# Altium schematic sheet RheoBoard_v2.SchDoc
size A0; SheetNumber: 1; SheetTotal: 3
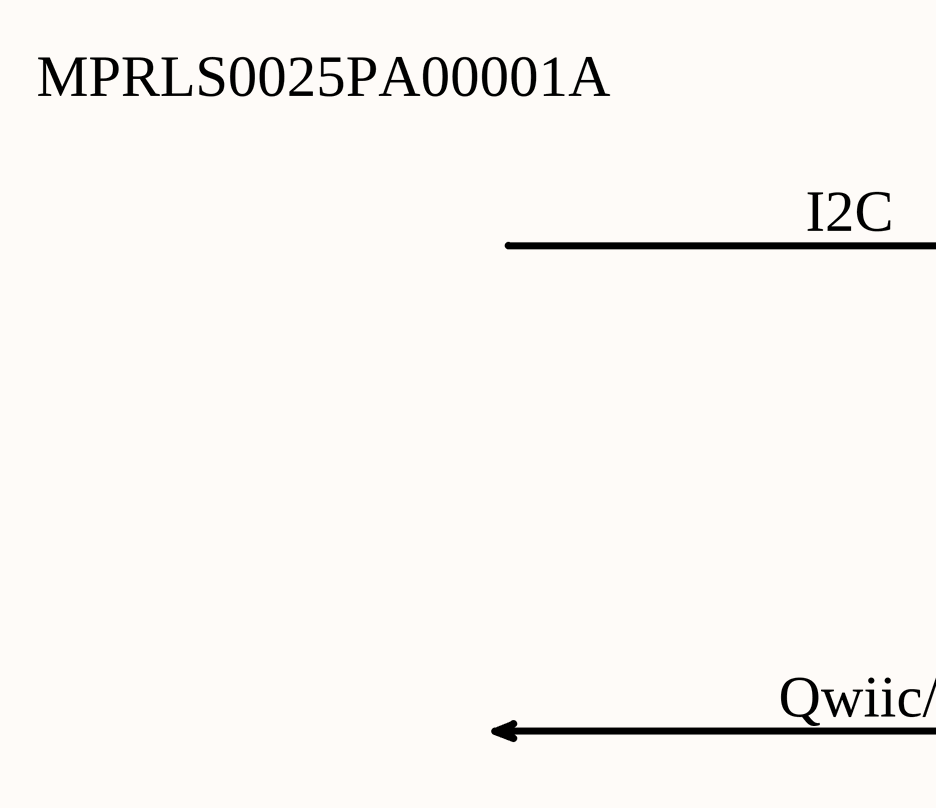
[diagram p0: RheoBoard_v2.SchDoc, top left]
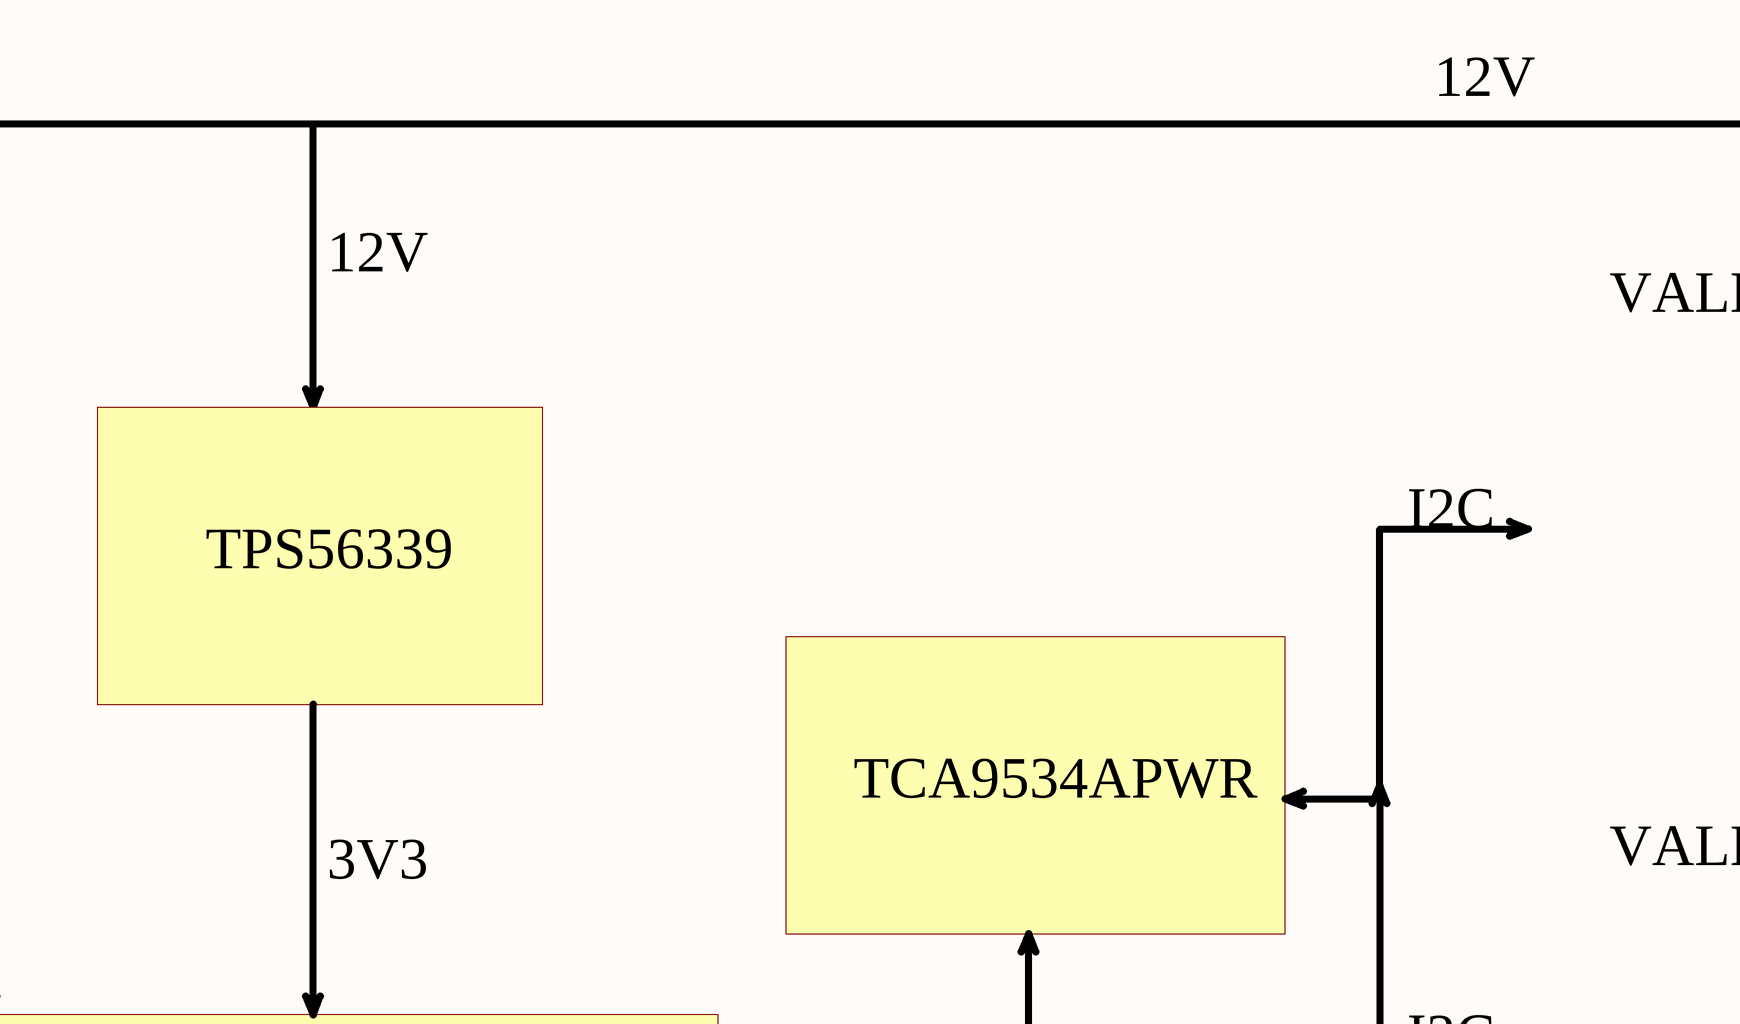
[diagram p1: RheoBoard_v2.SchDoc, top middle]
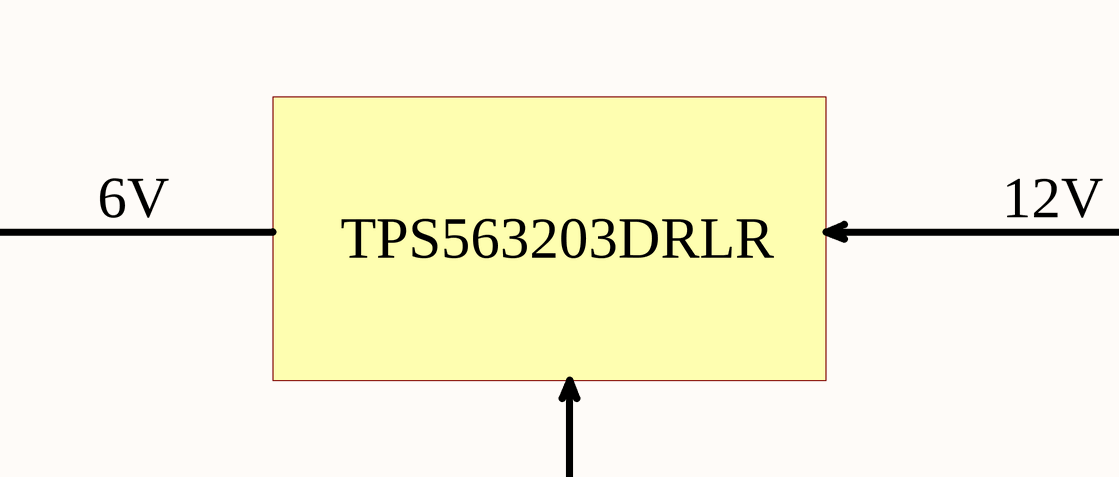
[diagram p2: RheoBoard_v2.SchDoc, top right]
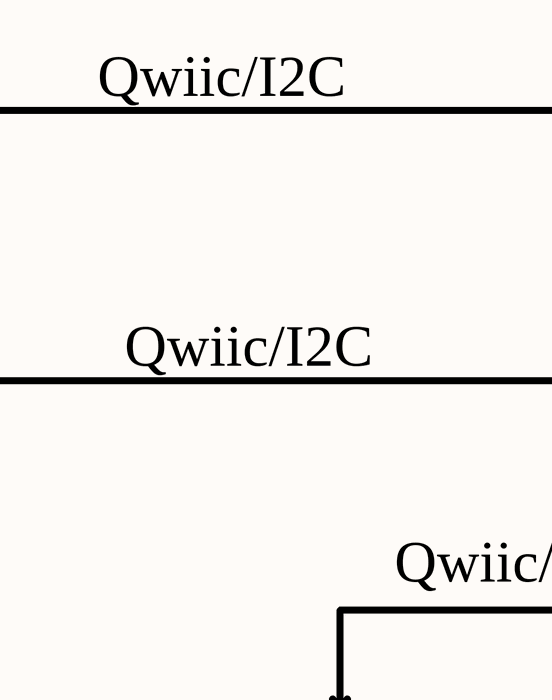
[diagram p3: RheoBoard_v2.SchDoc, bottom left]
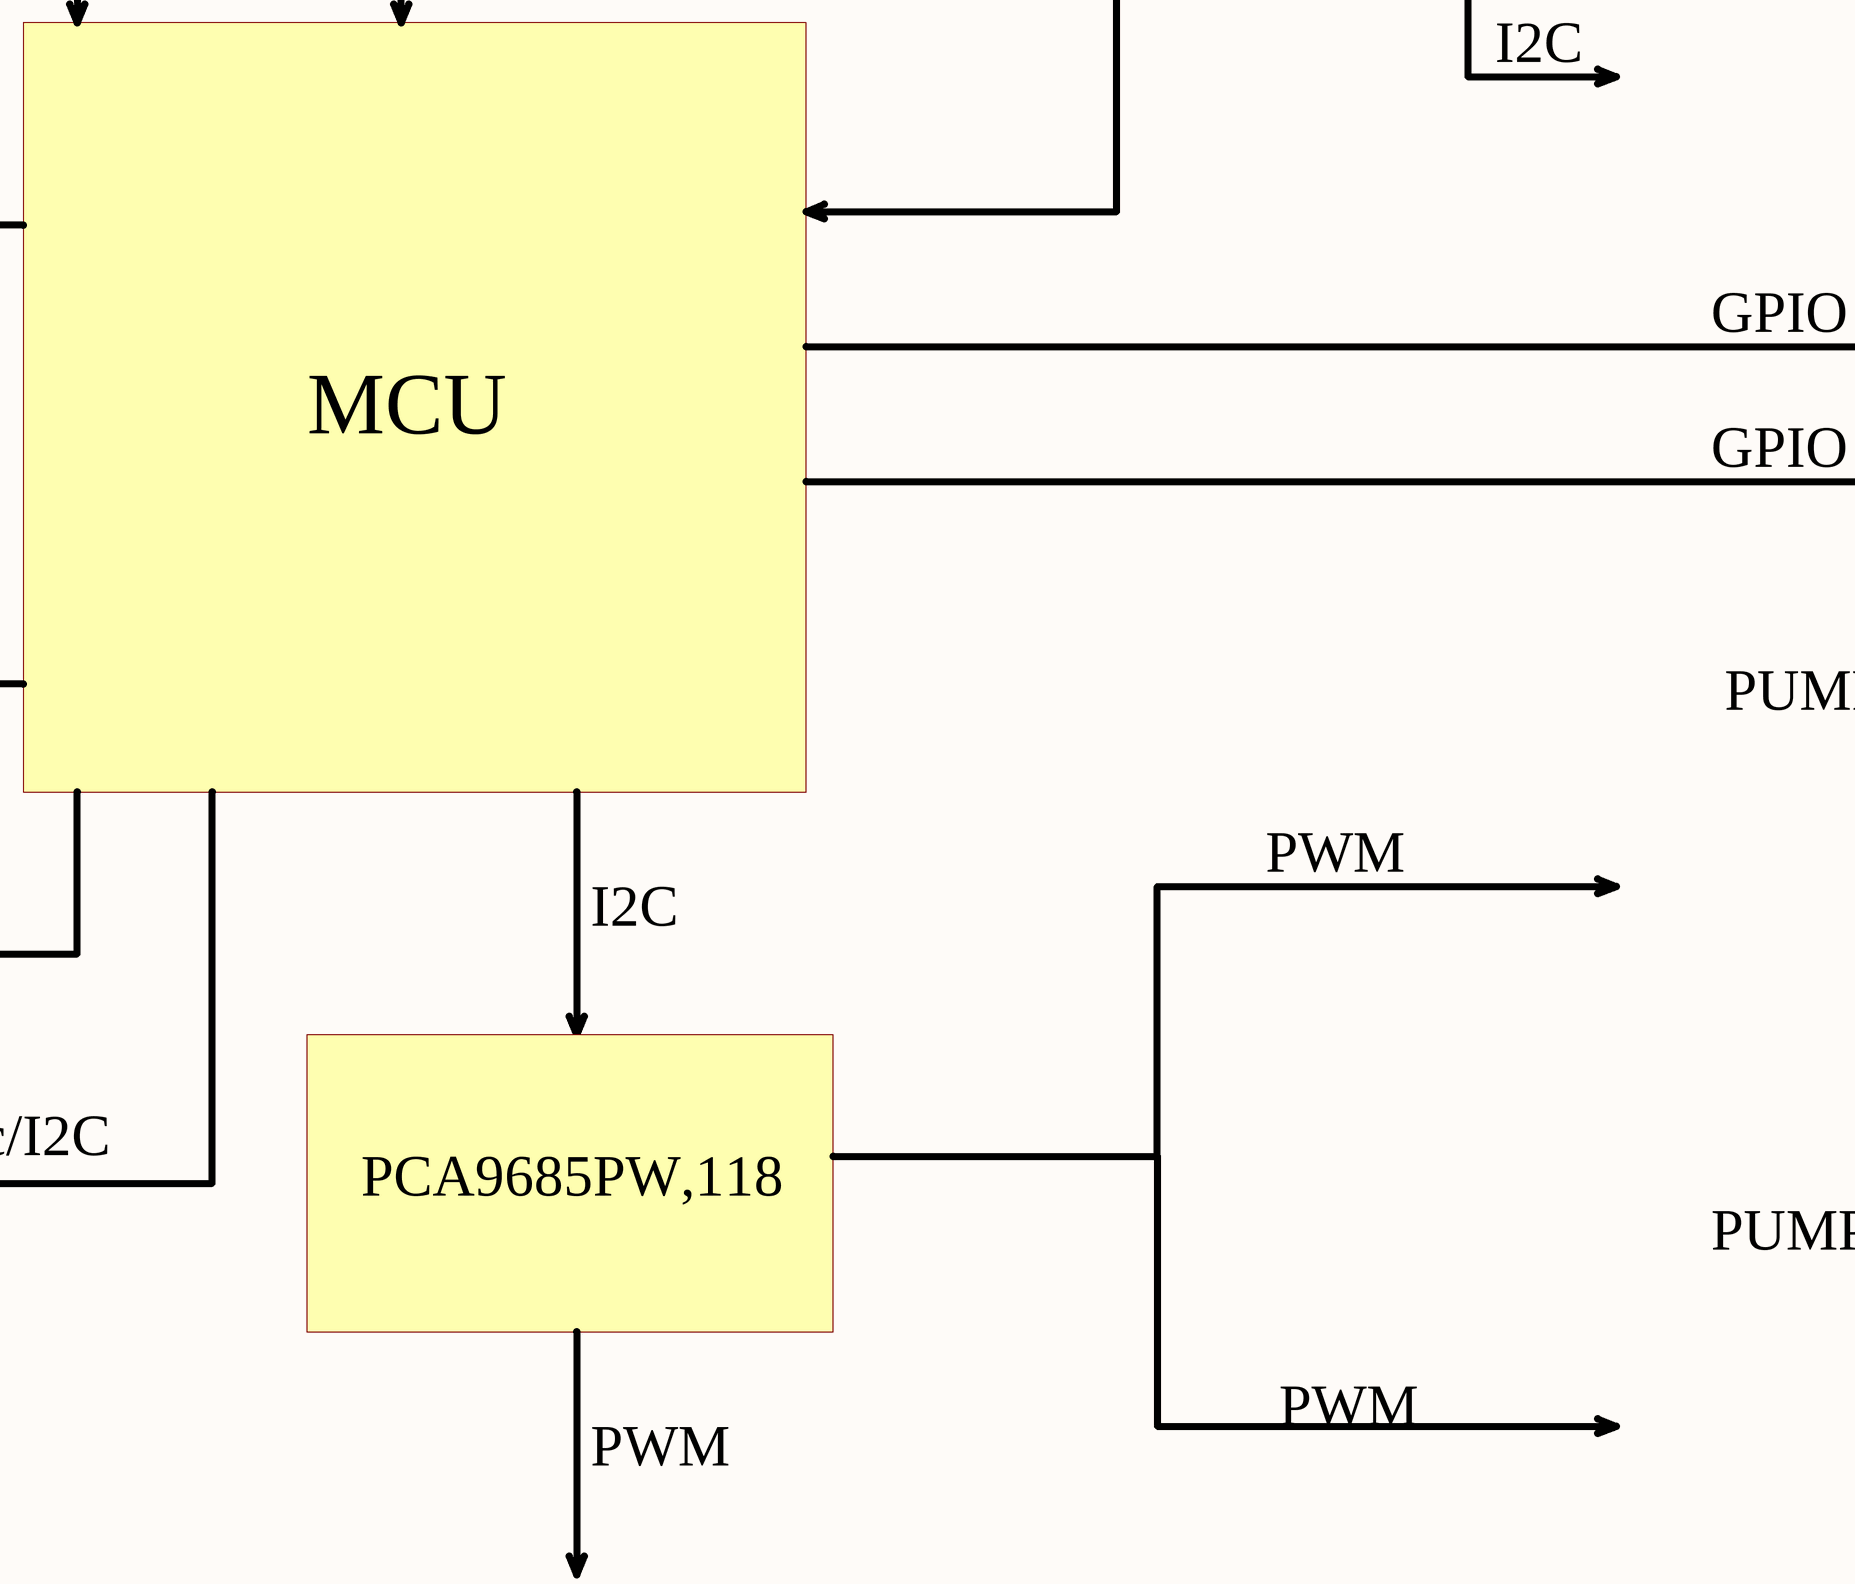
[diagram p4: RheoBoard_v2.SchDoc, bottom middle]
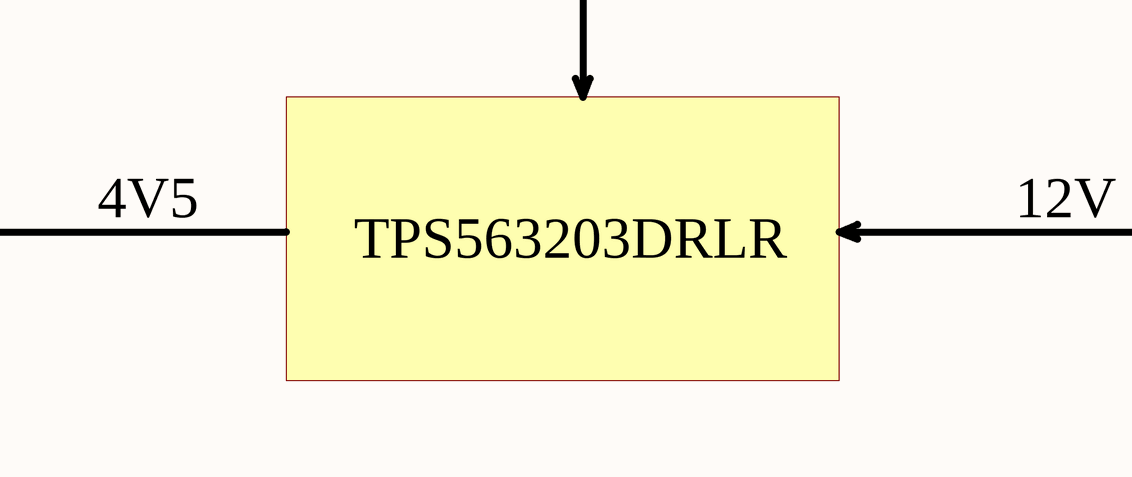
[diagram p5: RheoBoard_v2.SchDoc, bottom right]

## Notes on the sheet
- 12V
- VALE1
- I2C
- MPRLS0025PA00001A
- TPS56339
- TCA9534APWR
- 6V
- 3V3
- VALE2
- TPS563203DRLR
- Qwiic/I2C
- GPIO
- MCU
- PUMP1
- PWM
- 4V5
- PCA9685PW,118
- PUMP2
